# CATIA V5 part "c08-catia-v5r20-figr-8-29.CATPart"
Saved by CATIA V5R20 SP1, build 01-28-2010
Part number: Part1
Bounding box of the stored display mesh (mm): x 37.5 to 207.5, y 10 to 85, z 0 to 113
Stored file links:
  D:\v5_r20\psrt_files_downloaded\c08-catia-v5r20-prt\c08-catia-v5r20-figr-8-29.CATPart
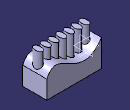
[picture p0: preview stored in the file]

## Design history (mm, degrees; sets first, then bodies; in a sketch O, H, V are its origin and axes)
Set1
  Plane1: type Offset, RefPlane xy-plane, Offset 113
Body1 (main body)
  Sketch1 on xy-plane, origin (0, 0, 0), H (1, 0, 0), V (0, 1, 0)
    line L1 (-37.5, 85) -> (37.5, 85)
    line L2 (37.5, 85) -> (37.5, -85)
    line L3 (37.5, -85) -> (-37.5, -85)
    line L4 (-37.5, -85) -> (-37.5, 85)
    axis line L5 (37.5, -85) -> (-37.5, 85)
    length L3 = 75
    length L2 = 170
    horizontal: L1 H, L3 H
    vertical: L2 V, L4 V
    midpoint: O L5
  Pad1: profile Sketch1, direction (0, 0, 1), length 83
  Sketch2 on face of Pad1, origin (37.5, 0, 0), H (0, 1, 0), V (0, 0, 1)
    spline S1 through (-85, 56.7422) (-58.5369, 80.0687) (-27.7952, 70.201) (85, 83)
    reference projected line E1 (85, 0) -> (85, 83) from edge [face of Pad1 | face of Pad1]
    reference projected line E2 (-85, 0) -> (-85, 83) from edge [face of Pad1 | face of Pad1]
    reference projected line E3 (-85, 83) -> (85, 83) from edge [face of Pad1 | face of Pad1]
    point P1 (85, 83)
    point P3 (-85, 56.7422)
    coincidence: P1 E1, P3 E2, P1 E3
  Pocket1: profile Sketch2, direction (-1, 0, 0), length 83
  Rotate1: ToTransfor Pocket1, Axis edge [face of Pad1 | face of Pad1], Angle 90
  Sketch3 on Plane1, origin (0, 0, 113), H (1, 0, 0), V (0, 1, 0)
    ellipse A1 centre (195.4286, 45.9861) semi-axes 14.9247, 8.8005 rotation 90
  Pad2: profile Sketch3, direction (0, 0, -1), up to face of Pocket1
  RectPattern1: of Pad2, direction 1 instances 7, spacing 24, along edge [face of Pad1 | face of Pad1]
